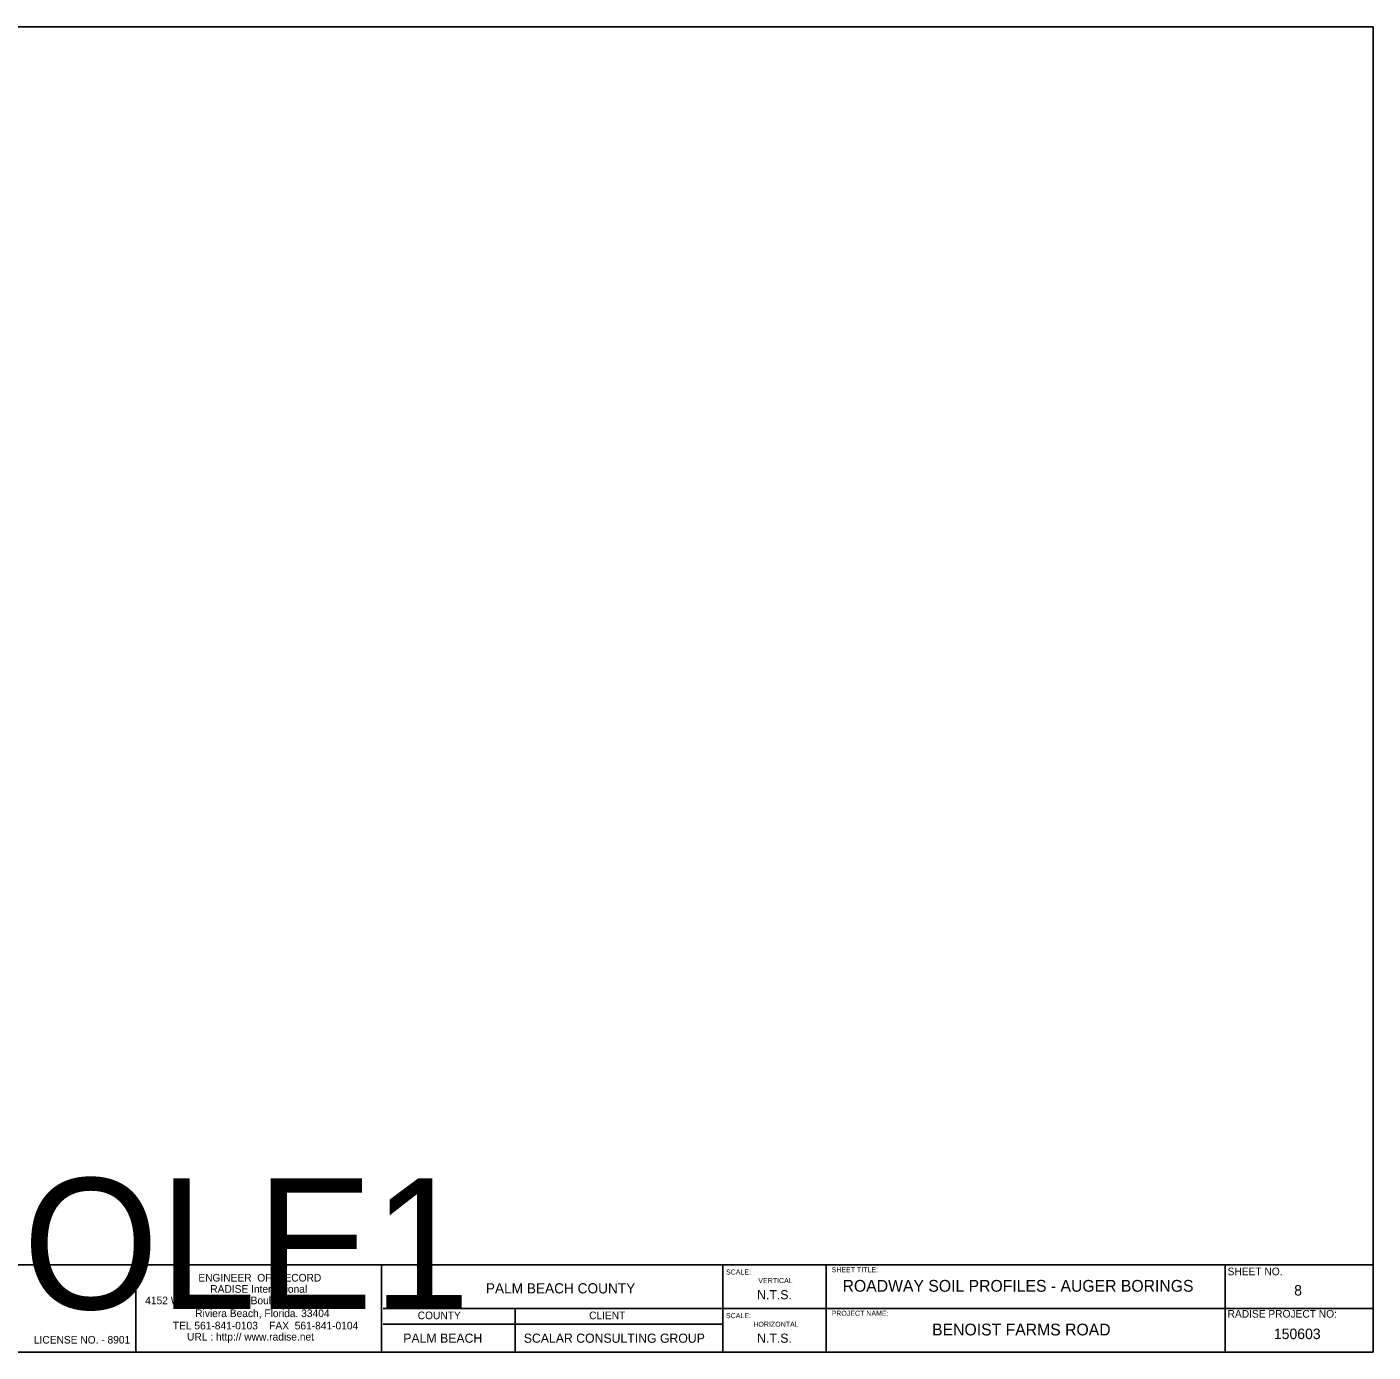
# Model space of a CAD drawing. Extents: x 0.6 to 16.4, y 0.2 to 10.3.
# Drawn here: x 6.16 to 16.45, y 0.16 to 10.29 of the extents above; entities that cross this region are included whole.
import ezdxf

# ---------------------------------------------------------------- set-up
doc = ezdxf.new("R2010")
doc.units = 0
for name, color, linetype in [('Level 1', 7, 'Continuous'), ('Level 23', 7, 'Continuous'), ('Level 24', 7, 'Continuous'), ('Level 46', 7, 'Continuous'), ('Level 63', 7, 'Continuous')]:
    doc.layers.add(name, color=color, linetype=linetype)

msp = doc.modelspace()

# ---------------------------------------------------------------- linework, layer by layer
at = {"layer": 'Level 23'}
for p, q in [((16.447, 0.161), (16.447, 10.287)), ((6.992, 0.161), (6.992, 0.827)), ((6.992, 0.161), (6.992, 0.827)), ((8.869, 0.161), (8.869, 0.827)), ((8.869, 0.161), (8.869, 0.827)), ((11.478, 0.161), (11.478, 0.827)), ((11.478, 0.161), (11.478, 0.827)), ((11.478, 0.161), (11.478, 0.827)), ((11.478, 0.161), (11.478, 0.827)), ((11.478, 0.161), (11.478, 0.827)), ((12.268, 0.161), (12.268, 0.827)), ((12.268, 0.161), (12.268, 0.827)), ((15.317, 0.161), (15.317, 0.827)), ((15.317, 0.161), (15.317, 0.827)), ((8.883, 0.494), (11.478, 0.494)), ((8.883, 0.494), (11.478, 0.494)), ((9.89, 0.494), (9.89, 0.161)), ((11.478, 0.494), (15.317, 0.494)), ((11.478, 0.494), (15.317, 0.494)), ((15.317, 0.494), (16.447, 0.494)), ((15.317, 0.494), (16.447, 0.494)), ((8.883, 0.373), (11.478, 0.373)), ((8.883, 0.373), (11.478, 0.373)), ((0.575, 0.161), (16.447, 0.161))]:
    msp.add_line(p, q, dxfattribs=at)
at = {"layer": 'Level 46'}
msp.add_line((0.573, 0.827), (16.447, 0.827), dxfattribs=at)
msp.add_line((0.573, 0.827), (16.447, 0.827), dxfattribs=at)
at = {"layer": 'Level 63'}
msp.add_lwpolyline([(0.575, 0.161), (16.447, 0.161), (16.447, 10.287), (0.575, 10.287), (0.575, 0.161)], dxfattribs=at)

# ---------------------------------------------------------------- texts
at = {"layer": 'Level 1'}
msp.add_text('OLE1', height=1, dxfattribs=at).set_placement((6.128, 0.489))
at = {"layer": 'Level 23'}
for s, height, p in [('ENGINEER  OF  RECORD', 0.05827, (7.47, 0.7)), ('SCALE:', 0.0389, (11.502, 0.753)), ('SCALE:', 0.0389, (11.502, 0.753)), ('SCALE:', 0.0389, (11.502, 0.753)), ('SCALE:', 0.0389, (11.502, 0.753)), ('SHEET TITLE:', 0.03887, (12.309, 0.771)), ('SHEET NO.', 0.0583, (15.335, 0.748)), ('RADISE International', 0.05827, (7.561, 0.614)), ('4152 West Blue Heron Boulevard, Suite 1114', 0.05827, (7.064, 0.526)), ('Riviera Beach, Florida. 33404', 0.05827, (7.446, 0.428)), ('COUNTY', 0.0583, (9.146, 0.412)), ('CLIENT', 0.0583, (10.456, 0.412)), ('SCALE:', 0.0389, (11.502, 0.42)), ('SCALE:', 0.0389, (11.502, 0.42)), ('SCALE:', 0.0389, (11.502, 0.42)), ('SCALE:', 0.0389, (11.502, 0.42)), ('PROJECT NAME:', 0.03887, (12.309, 0.438)), ('RADISE PROJECT NO:', 0.05827, (15.335, 0.424)), ('TEL 561-841-0103    FAX  561-841-0104', 0.05827, (7.275, 0.334)), ('                                                                URL : http:// www.radise.net', 0.05827, (5.998, 0.249)), ('LICENSE NO. - 8901', 0.05827, (6.213, 0.226))]:
    msp.add_text(s, height=height, dxfattribs=at).set_placement(p)
at = {"layer": 'Level 24'}
for s, height, p in [('VERTICAL', 0.0389, (11.749, 0.688)), ('PALM BEACH COUNTY ', 0.078, (9.667, 0.609)), ('N.T.S.', 0.07, (11.74, 0.564)), ('ROADWAY SOIL PROFILES - AUGER BORINGS', 0.09, (12.393, 0.622)), ('8', 0.08, (15.844, 0.593)), ('HORIZONTAL', 0.0389, (11.711, 0.354)), ('BENOIST FARMS ROAD', 0.09, (13.077, 0.288)), ('150603', 0.08, (15.689, 0.26)), ('PALM BEACH', 0.07, (9.036, 0.232)), ('SCALAR CONSULTING GROUP', 0.07, (9.957, 0.232)), ('N.T.S.', 0.07, (11.74, 0.232))]:
    msp.add_text(s, height=height, dxfattribs=at).set_placement(p)

doc.saveas('drawing.dxf')
